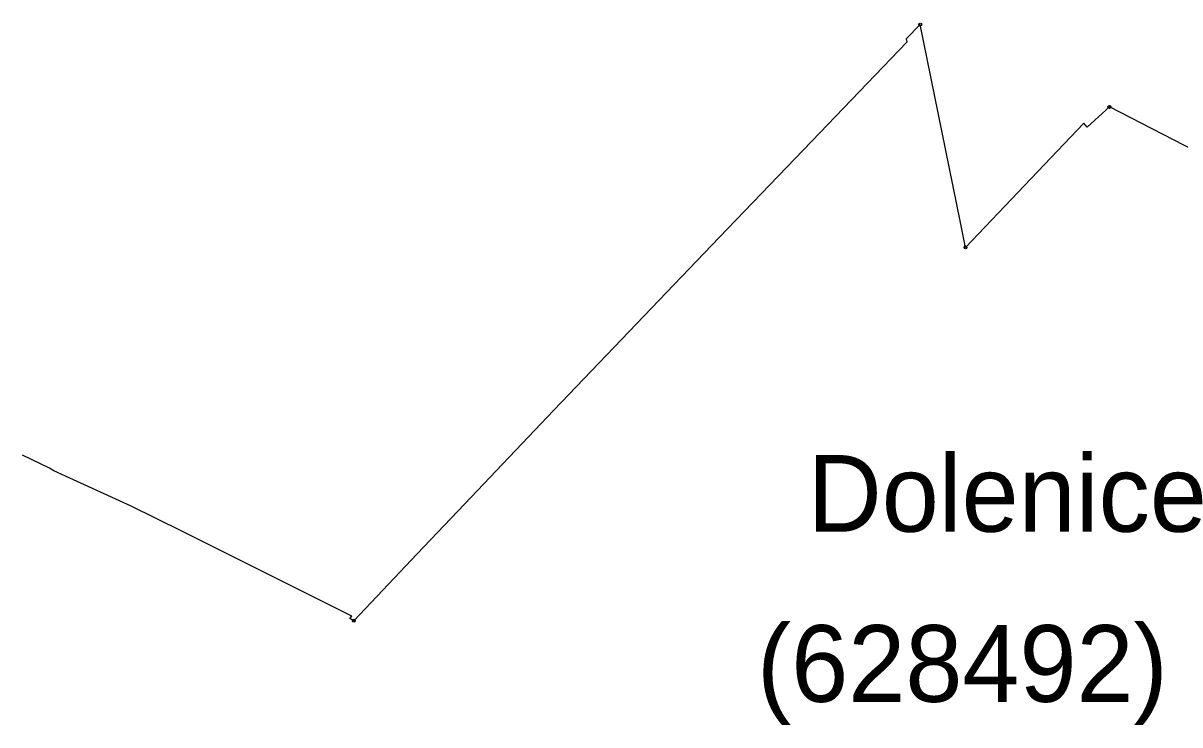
# Model space of a CAD drawing. Extents: x -623137 to -616791, y -1192758 to -1186540.
# Drawn here: x -620059 to -618853, y -1190531 to -1189799 of the extents above; entities that cross this region are included whole.
import ezdxf

# ---------------------------------------------------------------- set-up
doc = ezdxf.new("R2010")
doc.units = 0
for name, color, linetype in [('Legenda', 7, 'Continuous'), ('Vrstva 13', 7, 'Continuous'), ('Vzdy červené', 7, 'Continuous')]:
    doc.layers.add(name, color=color, linetype=linetype)

msp = doc.modelspace()

# ---------------------------------------------------------------- linework, layer by layer
at = {"layer": 'Vrstva 13'}
for p, q in [((-619124, -1189800.7), (-619138.8, -1189815.7)), ((-619082.4, -1190005.4), (-619124, -1189800.7)), ((-619138.1, -1189819.1), (-619236.9, -1189922.1)), ((-619138.8, -1189815.7), (-619138.1, -1189819.1)), ((-618926.9, -1189886.6), (-618941.9, -1189900.5)), ((-618354.5, -1190180.6), (-618926.9, -1189886.6)), ((-618953.4, -1189903.6), (-619035.9, -1189989.9)), ((-618950.1, -1189907.6), (-618953.4, -1189903.6)), ((-618953.4, -1189903.6), (-618953.4, -1189903.6)), ((-618941.9, -1189900.5), (-618950.1, -1189907.6)), ((-619236.9, -1189922.1), (-619333.8, -1190022.6)), ((-619035.9, -1189989.9), (-619076.8, -1190033)), ((-619035.9, -1189989.9), (-619035.9, -1189989.9)), ((-619076.8, -1190033), (-619082.4, -1190005.4)), ((-619082.4, -1190005.4), (-619082.4, -1190005.4)), ((-619333.8, -1190022.6), (-619506.1, -1190202.9)), ((-619333.8, -1190022.6), (-619333.8, -1190022.6)), ((-619506.1, -1190202.9), (-619599.2, -1190300.9)), ((-620031.9, -1190263.3), (-620059.8, -1190249.7)), ((-620027.3, -1190266), (-620031.9, -1190263.3)), ((-620002.8, -1190277.2), (-620027.3, -1190266)), ((-619946.7, -1190303), (-620002.8, -1190277.2)), ((-619893.9, -1190329.1), (-619946.7, -1190303)), ((-619599.2, -1190300.9), (-619648.5, -1190352.7)), ((-619716.7, -1190417.8), (-619893.9, -1190329.1)), ((-619648.5, -1190352.7), (-619714.5, -1190422.4)), ((-619648.5, -1190352.7), (-619648.5, -1190352.7)), ((-619718.7, -1190420), (-619716.7, -1190417.8)), ((-619714.5, -1190422.4), (-619718.7, -1190420)), ((-619716.7, -1190417.8), (-619716.7, -1190417.8)), ((-619716.7, -1190417.8), (-619716.7, -1190417.8))]:
    msp.add_line(p, q, dxfattribs=at)
at = {"layer": 'Vzdy červené'}
for centre in [(-619124, -1189800.7), (-618926.9, -1189886.6), (-619076.8, -1190033), (-619714.5, -1190422.4)]:
    msp.add_circle(centre, 1.5, dxfattribs=at)

# ---------------------------------------------------------------- texts
at = {"layer": 'Legenda'}
for s, p in [('Dolenice', (-619241.4, -1190329.6)), ('(628492)', (-619294.2, -1190507))]:
    msp.add_text(s, height=80, dxfattribs=at).set_placement(p)

doc.saveas('drawing.dxf')
